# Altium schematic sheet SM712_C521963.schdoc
size 127 x 101 mm
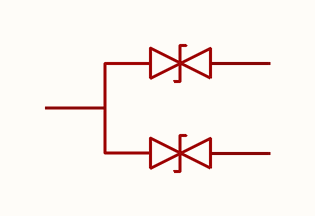
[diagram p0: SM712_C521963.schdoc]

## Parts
D?  sm712_c521963  [SOT-23-3_L2.9-W1.3-P1.90-LS2.4-BR]  (value not drawn)

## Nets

Not connected (* = marked no-connect by the designer): D? 1 2 3

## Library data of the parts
D? = sm712_c521963: 极性:双向;反向截止电压(Vrwm):12V；7V;最大钳位电压:15V；25V;峰值脉冲电流(Ipp):7A;峰值脉冲功率(Ppp):150W;击穿电压:7.5V；13.3V;; Manufacturer: TECH PUBLIC(台舟); ManufacturerPart: SM712; AddInBom: yes; ModelId: c62791f0466c4ae2a892c056b845b0ca; ModelName: SOT-23-3P_L2.9-W1.3-H1.0-LS2.4-P0.95; ModelTransform: 98.425,114.173,0,180,0,0,0.0005,-0.0005,0; polarity: 双向; Reverse Stand-Off Voltage (Vrwm): 12V；7V; Peak Pulse Current (Ipp): 7A; Peak Pulse Power Dissipation (Ppp): 150W; Reverse Leakage Current (Ir): 500nA；10nA; Number of Lines: 双路; level of protection: IEC 61000-4-2; Type: ESD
